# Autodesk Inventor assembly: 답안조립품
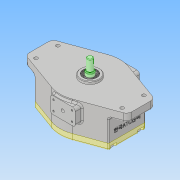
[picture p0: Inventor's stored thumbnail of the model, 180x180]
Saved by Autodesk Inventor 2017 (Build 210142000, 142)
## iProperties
Part Number: 답안조립품
Material: 일반
Document SubType Name: Assembly
Designer: mrc
Author: mrc
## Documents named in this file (14)
- C:\Users\mrc\Desktop\731106V1003\답안조립품.iam
- C:\Users\mrc\Desktop\731106V1003\본체.ipt
- C:\Users\mrc\Desktop\731106V1003\DU 부시.ipt
- C:\Users\mrc\Desktop\731106V1003\O링 G90.ipt
- C:\Users\mrc\Desktop\731106V1003\내접기어.ipt
- C:\Users\mrc\Desktop\731106V1003\스퍼기어.ipt
- C:\Users\mrc\Desktop\731106V1003\오일 실 14 25 4.ipt
- C:\Users\mrc\Desktop\731106V1003\오일레스 부시.ipt
- C:\Users\mrc\Desktop\731106V1003\육각 소켓 머리 볼트 M4 x 30.ipt
- C:\Users\mrc\Desktop\731106V1003\육각 소켓 머리 볼트 M6 x 12.ipt
- C:\Users\mrc\Desktop\731106V1003\축.ipt
- C:\Users\mrc\Desktop\731106V1003\커버.ipt
- C:\Users\mrc\Desktop\731106V1003\크레센트.ipt
- C:\Users\mrc\Desktop\731106V1003\평행 키 5x5x22.ipt
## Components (2 placed, 2 different names)
1. DU 부시:1
2. O링 G90:1
